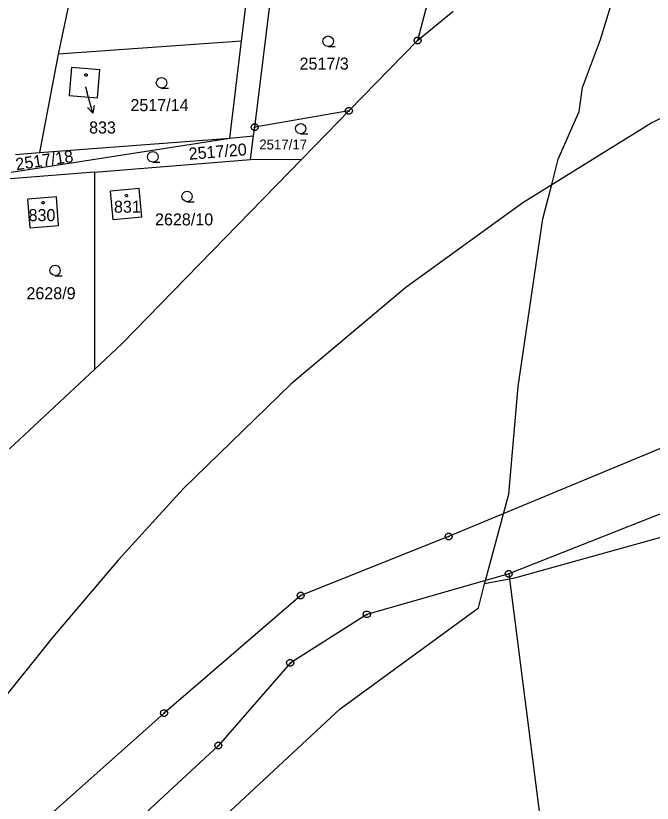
# Model space of a CAD drawing. Extents: x -760611 to -758411, y -1176479 to -1174807.
# Drawn here: x -759368.4 to -759278.5, y -1175293 to -1175181.7 of the extents above; entities that cross this region are included whole.
import ezdxf

# ---------------------------------------------------------------- set-up
doc = ezdxf.new("R2010")
doc.units = 0
for name, color, linetype in [('1', 7, 'Continuous'), ('11', 7, 'Continuous'), ('12', 7, 'Continuous'), ('2', 7, 'Continuous'), ('3', 7, 'Continuous'), ('5', 7, 'Continuous'), ('6', 7, 'Continuous'), ('7', 7, 'Continuous'), ('8', 7, 'Continuous')]:
    doc.layers.add(name, color=color, linetype=linetype)

msp = doc.modelspace()

# ---------------------------------------------------------------- linework, layer by layer
at = {"layer": '1'}
for p, q in [((-759336.51, -1175185.32), (-759334.73, -1175170.49)), ((-759359.46, -1175173.34), (-759362.4, -1175187.18)), ((-759309.78, -1175178.15), (-759311.62, -1175185.22)), ((-759334.64, -1175197.47), (-759332.57, -1175180.66)), ((-759311.62, -1175185.22), (-759306.6, -1175181.08)), ((-759336.51, -1175185.32), (-759362.4, -1175187.18)), ((-759338.17, -1175199.04), (-759336.51, -1175185.32)), ((-759311.62, -1175185.22), (-759321.33, -1175195.19)), ((-759362.4, -1175187.18), (-759365.05, -1175201.07)), ((-759360.52, -1175189), (-759360.87, -1175193.02)), ((-759360.52, -1175189), (-759356.52, -1175189.34)), ((-759356.87, -1175193.33), (-759356.52, -1175189.34)), ((-759360.87, -1175193.02), (-759356.87, -1175193.33)), ((-759321.33, -1175195.19), (-759334.64, -1175197.47)), ((-759321.33, -1175195.19), (-759322.73, -1175196.62)), ((-759322.73, -1175196.62), (-759327.96, -1175201.99)), ((-759334.79, -1175198.68), (-759334.64, -1175197.47)), ((-759338.17, -1175199.04), (-759334.79, -1175198.68)), ((-759335.21, -1175202.06), (-759334.79, -1175198.68)), ((-759369.05, -1175203.82), (-759338.17, -1175199.04)), ((-759365.05, -1175201.07), (-759338.17, -1175199.04)), ((-759368.43, -1175201.33), (-759365.05, -1175201.07)), ((-759357.27, -1175203.83), (-759335.21, -1175202.06)), ((-759327.96, -1175201.99), (-759353.35, -1175228.06)), ((-759335.21, -1175202.06), (-759327.96, -1175201.99)), ((-759357.27, -1175203.83), (-759369.21, -1175204.76)), ((-759357.27, -1175203.83), (-759357.28, -1175231.73)), ((-759350.97, -1175206.16), (-759355.03, -1175206.54)), ((-759354.65, -1175210.59), (-759355.03, -1175206.54)), ((-759350.59, -1175210.21), (-759350.97, -1175206.16)), ((-759362.63, -1175207.33), (-759366.68, -1175207.66)), ((-759366.36, -1175211.69), (-759366.68, -1175207.66)), ((-759362.34, -1175211.37), (-759362.63, -1175207.33)), ((-759350.59, -1175210.21), (-759354.65, -1175210.59)), ((-759366.36, -1175211.69), (-759362.34, -1175211.37)), ((-759353.35, -1175228.06), (-759357.28, -1175231.73)), ((-759357.28, -1175231.73), (-759369.26, -1175242.94)), ((-759268.1, -1175239.07), (-759307.24, -1175255.34)), ((-759263.85, -1175246.81), (-759298.74, -1175260.61)), ((-759307.24, -1175255.34), (-759328.13, -1175263.67)), ((-759298.74, -1175260.61), (-759318.79, -1175266.34)), ((-759298.74, -1175260.61), (-759285.43, -1175364.72)), ((-759328.13, -1175263.67), (-759347.43, -1175280.29)), ((-759318.79, -1175266.34), (-759329.62, -1175273.21)), ((-759329.62, -1175273.21), (-759339.76, -1175284.87)), ((-759347.43, -1175280.29), (-759389.73, -1175317.99)), ((-759339.76, -1175284.87), (-759363.75, -1175307.07))]:
    msp.add_line(p, q, dxfattribs=at)
at = {"layer": '11'}
for points in [[(-759302.17, -1175262.03), (-759302.03, -1175261.55), (-759299.47, -1175252.11), (-759298.73, -1175249.35), (-759297.4, -1175234.13), (-759293.92, -1175210.45), (-759292.63, -1175205.38), (-759291.77, -1175202), (-759288.78, -1175195.24), (-759288.34, -1175191.86), (-759285.77, -1175185.1), (-759279.57, -1175164.75), (-759276.09, -1175153.33), (-759274.19, -1175147.08), (-759269.92, -1175137.79), (-759267.35, -1175132.72), (-759260.94, -1175117.52), (-759255.81, -1175107.39), (-759254.95, -1175102.32), (-759253.24, -1175098.94), (-759251.12, -1175100.22), (-759246.85, -1175092.2)], [(-759132.3, -1175318.61), (-759156.06, -1175311), (-759167.91, -1175305.86), (-759171.08, -1175304.18), (-759174.75, -1175302.24), (-759227.58, -1175274.25), (-759234.21, -1175271.67), (-759244.09, -1175267.82), (-759256.38, -1175263.95), (-759258.05, -1175258.44), (-759258.03, -1175252.52), (-759275.43, -1175254.97), (-759297.92, -1175261.21), (-759298.65, -1175261.35), (-759302.17, -1175262.03)], [(-759393.16, -1175334.36), (-759387.3, -1175330.9), (-759368.94, -1175320.09), (-759362.69, -1175315.26), (-759351.51, -1175306.64), (-759322.58, -1175279.7), (-759303.02, -1175265.41), (-759302.17, -1175262.03)]]:
    msp.add_lwpolyline(points, dxfattribs=at)
at = {"layer": '12'}
for p, q in [((-759360.52, -1175189), (-759360.87, -1175193.02)), ((-759360.52, -1175189), (-759356.52, -1175189.34)), ((-759356.87, -1175193.33), (-759356.52, -1175189.34)), ((-759360.87, -1175193.02), (-759356.87, -1175193.33)), ((-759350.97, -1175206.16), (-759355.03, -1175206.54)), ((-759354.65, -1175210.59), (-759355.03, -1175206.54)), ((-759350.59, -1175210.21), (-759350.97, -1175206.16)), ((-759362.63, -1175207.33), (-759366.68, -1175207.66)), ((-759366.36, -1175211.69), (-759366.68, -1175207.66)), ((-759362.34, -1175211.37), (-759362.63, -1175207.33)), ((-759350.59, -1175210.21), (-759354.65, -1175210.59)), ((-759366.36, -1175211.69), (-759362.34, -1175211.37))]:
    msp.add_line(p, q, dxfattribs=at)
at = {"layer": '3'}
for points in [[(-759324.25, -1175186.07), (-759324.63, -1175185.97), (-759324.9, -1175185.7), (-759325, -1175185.33), (-759324.9, -1175184.96), (-759324.63, -1175184.69), (-759324.26, -1175184.59), (-759323.89, -1175184.69), (-759323.62, -1175184.96), (-759323.52, -1175185.34), (-759323.62, -1175185.72), (-759323.89, -1175185.99), (-759324.27, -1175186.09), (-759323.27, -1175186.09)], [(-759347.79, -1175191.94), (-759348.17, -1175191.84), (-759348.44, -1175191.57), (-759348.54, -1175191.2), (-759348.44, -1175190.83), (-759348.17, -1175190.56), (-759347.8, -1175190.46), (-759347.43, -1175190.56), (-759347.16, -1175190.83), (-759347.06, -1175191.21), (-759347.16, -1175191.59), (-759347.43, -1175191.86), (-759347.81, -1175191.96), (-759346.81, -1175191.96)], [(-759328.13, -1175198.42), (-759328.51, -1175198.32), (-759328.78, -1175198.05), (-759328.88, -1175197.68), (-759328.78, -1175197.31), (-759328.51, -1175197.04), (-759328.14, -1175196.94), (-759327.77, -1175197.04), (-759327.5, -1175197.31), (-759327.4, -1175197.69), (-759327.5, -1175198.07), (-759327.77, -1175198.34), (-759328.15, -1175198.44), (-759327.15, -1175198.44)], [(-759349.02, -1175202.41), (-759349.4, -1175202.31), (-759349.67, -1175202.04), (-759349.77, -1175201.67), (-759349.67, -1175201.3), (-759349.4, -1175201.03), (-759349.03, -1175200.93), (-759348.66, -1175201.03), (-759348.39, -1175201.3), (-759348.29, -1175201.68), (-759348.39, -1175202.06), (-759348.66, -1175202.33), (-759349.04, -1175202.43), (-759348.04, -1175202.43)], [(-759344.19, -1175208.01), (-759344.57, -1175207.91), (-759344.84, -1175207.64), (-759344.94, -1175207.27), (-759344.84, -1175206.9), (-759344.57, -1175206.63), (-759344.2, -1175206.53), (-759343.83, -1175206.63), (-759343.56, -1175206.9), (-759343.46, -1175207.28), (-759343.56, -1175207.66), (-759343.83, -1175207.93), (-759344.21, -1175208.03), (-759343.21, -1175208.03)], [(-759362.83, -1175218.46), (-759363.21, -1175218.36), (-759363.48, -1175218.09), (-759363.58, -1175217.72), (-759363.48, -1175217.35), (-759363.21, -1175217.08), (-759362.84, -1175216.98), (-759362.47, -1175217.08), (-759362.2, -1175217.35), (-759362.1, -1175217.73), (-759362.2, -1175218.11), (-759362.47, -1175218.38), (-759362.85, -1175218.48), (-759361.85, -1175218.48)]]:
    msp.add_lwpolyline(points, dxfattribs=at)
at = {"layer": '5'}
for points in [[(-759358.48, -1175189.94), (-759358.38, -1175189.96), (-759358.33, -1175190.05), (-759358.31, -1175190.11), (-759358.33, -1175190.2), (-759358.41, -1175190.27), (-759358.48, -1175190.28), (-759358.57, -1175190.25), (-759358.63, -1175190.19), (-759358.65, -1175190.11), (-759358.63, -1175190.02), (-759358.55, -1175189.95)], [(-759352.76, -1175206.97), (-759352.66, -1175206.99), (-759352.61, -1175207.08), (-759352.59, -1175207.14), (-759352.61, -1175207.23), (-759352.69, -1175207.3), (-759352.76, -1175207.31), (-759352.85, -1175207.28), (-759352.91, -1175207.22), (-759352.93, -1175207.14), (-759352.91, -1175207.05), (-759352.83, -1175206.98)], [(-759364.53, -1175207.98), (-759364.43, -1175208), (-759364.38, -1175208.09), (-759364.36, -1175208.15), (-759364.38, -1175208.24), (-759364.46, -1175208.31), (-759364.53, -1175208.32), (-759364.62, -1175208.29), (-759364.68, -1175208.23), (-759364.7, -1175208.15), (-759364.68, -1175208.06), (-759364.6, -1175207.99)]]:
    msp.add_lwpolyline(points, close=True, dxfattribs=at)
at = {"layer": '6'}
for p, q in [((-759259.71, -1175187.11), (-759278.52, -1175196.88)), ((-759278.52, -1175196.88), (-759296.75, -1175208.15)), ((-759296.75, -1175208.15), (-759313.29, -1175220.12)), ((-759313.29, -1175220.12), (-759329.55, -1175233.79)), ((-759329.55, -1175233.79), (-759344.74, -1175248.59)), ((-759344.74, -1175248.59), (-759353.93, -1175258.69)), ((-759353.93, -1175258.69), (-759363.2, -1175269.62)), ((-759363.2, -1175269.62), (-759371.95, -1175280.48))]:
    msp.add_line(p, q, dxfattribs=at)
at = {"layer": '7'}
for p in [(-759358.55, -1175191.76), (-759357.51, -1175195.51)]:
    msp.add_line(p, (-759358.31, -1175192.62), dxfattribs=at)
msp.add_lwpolyline([(-759357.3, -1175194.42), (-759357.51, -1175195.51), (-759358.26, -1175194.68)], dxfattribs=at)
at = {"layer": '8'}
for p, q in [((-759311.74, -1175185.22), (-759311.5, -1175185.22)), ((-759321.45, -1175195.19), (-759321.21, -1175195.19)), ((-759334.76, -1175197.47), (-759334.52, -1175197.47)), ((-759307.36, -1175255.34), (-759307.12, -1175255.34)), ((-759298.86, -1175260.61), (-759298.62, -1175260.61)), ((-759328.25, -1175263.67), (-759328.01, -1175263.67)), ((-759318.91, -1175266.34), (-759318.67, -1175266.34)), ((-759329.74, -1175273.21), (-759329.5, -1175273.21)), ((-759347.55, -1175280.29), (-759347.31, -1175280.29)), ((-759339.88, -1175284.87), (-759339.64, -1175284.87))]:
    msp.add_line(p, q, dxfattribs=at)
for points in [[(-759311.47, -1175184.74), (-759311.22, -1175184.92), (-759311.12, -1175185.21), (-759311.22, -1175185.5), (-759311.47, -1175185.68), (-759311.78, -1175185.68), (-759312.03, -1175185.5), (-759312.13, -1175185.21), (-759312.03, -1175184.92), (-759311.78, -1175184.74)], [(-759321.18, -1175194.71), (-759320.93, -1175194.89), (-759320.83, -1175195.18), (-759320.93, -1175195.47), (-759321.18, -1175195.65), (-759321.49, -1175195.65), (-759321.74, -1175195.47), (-759321.84, -1175195.18), (-759321.74, -1175194.89), (-759321.49, -1175194.71)], [(-759334.49, -1175196.99), (-759334.24, -1175197.17), (-759334.14, -1175197.46), (-759334.24, -1175197.75), (-759334.49, -1175197.93), (-759334.8, -1175197.93), (-759335.05, -1175197.75), (-759335.15, -1175197.46), (-759335.05, -1175197.17), (-759334.8, -1175196.99)], [(-759307.09, -1175254.86), (-759306.84, -1175255.04), (-759306.74, -1175255.33), (-759306.84, -1175255.62), (-759307.09, -1175255.8), (-759307.4, -1175255.8), (-759307.65, -1175255.62), (-759307.75, -1175255.33), (-759307.65, -1175255.04), (-759307.4, -1175254.86)], [(-759298.59, -1175260.13), (-759298.34, -1175260.31), (-759298.24, -1175260.6), (-759298.34, -1175260.89), (-759298.59, -1175261.07), (-759298.9, -1175261.07), (-759299.15, -1175260.89), (-759299.25, -1175260.6), (-759299.15, -1175260.31), (-759298.9, -1175260.13)], [(-759327.98, -1175263.19), (-759327.73, -1175263.37), (-759327.63, -1175263.66), (-759327.73, -1175263.95), (-759327.98, -1175264.13), (-759328.29, -1175264.13), (-759328.54, -1175263.95), (-759328.64, -1175263.66), (-759328.54, -1175263.37), (-759328.29, -1175263.19)], [(-759318.64, -1175265.86), (-759318.39, -1175266.04), (-759318.29, -1175266.33), (-759318.39, -1175266.62), (-759318.64, -1175266.8), (-759318.95, -1175266.8), (-759319.2, -1175266.62), (-759319.3, -1175266.33), (-759319.2, -1175266.04), (-759318.95, -1175265.86)], [(-759329.47, -1175272.73), (-759329.22, -1175272.91), (-759329.12, -1175273.2), (-759329.22, -1175273.49), (-759329.47, -1175273.67), (-759329.78, -1175273.67), (-759330.03, -1175273.49), (-759330.13, -1175273.2), (-759330.03, -1175272.91), (-759329.78, -1175272.73)], [(-759347.28, -1175279.81), (-759347.03, -1175279.99), (-759346.93, -1175280.28), (-759347.03, -1175280.57), (-759347.28, -1175280.75), (-759347.59, -1175280.75), (-759347.84, -1175280.57), (-759347.94, -1175280.28), (-759347.84, -1175279.99), (-759347.59, -1175279.81)], [(-759339.61, -1175284.39), (-759339.36, -1175284.57), (-759339.26, -1175284.86), (-759339.36, -1175285.15), (-759339.61, -1175285.33), (-759339.92, -1175285.33), (-759340.17, -1175285.15), (-759340.27, -1175284.86), (-759340.17, -1175284.57), (-759339.92, -1175284.39)]]:
    msp.add_lwpolyline(points, close=True, dxfattribs=at)

# ---------------------------------------------------------------- texts
at = {"layer": '2'}
for s, height, p in [('2517/3', 1.7, (-759328.3, -1175189.34)), ('833', 0.1, (-759358.68, -1175191.76)), ('2517/14', 1.7, (-759352.2, -1175195.21)), ('2517/17', 1.4, (-759334, -1175200.63)), ('831', 1.7, (-759354.52, -1175209.57)), ('830', 1.7, (-759366.59, -1175210.76)), ('2628/10', 1.7, (-759348.72, -1175211.36)), ('2628/9', 1.7, (-759366.89, -1175221.8))]:
    msp.add_text(s, height=height, dxfattribs=at).set_placement(p)
for s, rotation, p in [('2517/20', 4.5264, (-759343.9, -1175202.09)), ('2517/18', 8.3079, (-759368.3, -1175203.57))]:
    msp.add_text(s, height=1.7, rotation=rotation, dxfattribs=at).set_placement(p)
at = {"layer": '7'}
msp.add_text('833', height=1.7, dxfattribs=at).set_placement((-759358.04, -1175198.37))

doc.saveas('drawing.dxf')
